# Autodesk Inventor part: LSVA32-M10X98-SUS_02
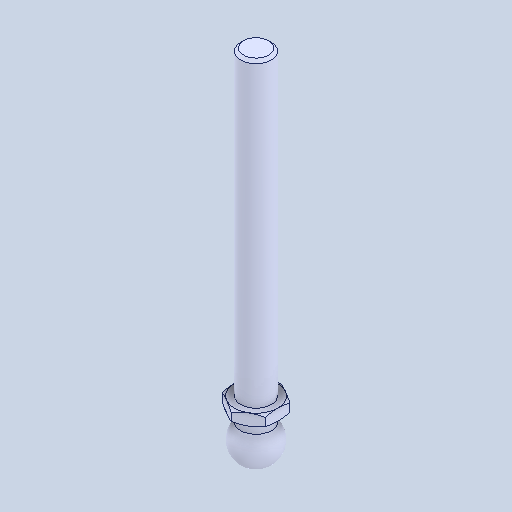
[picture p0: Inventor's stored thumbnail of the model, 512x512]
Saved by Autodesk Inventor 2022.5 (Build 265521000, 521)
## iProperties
Created: 2024-08
Part Number: LSVA32-M10X98-SUS_02
Material: 一般
Document SubType Name: Modeling
Designer: ImaoCorp
Density: 1 g/cm^3
Appearance: 既定
Author: ImaoCorp
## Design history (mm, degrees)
feature "LSVA32-M10X98-SUS_02"
node "ソリッド1"
